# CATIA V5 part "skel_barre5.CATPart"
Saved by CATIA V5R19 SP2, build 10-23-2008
Part number: skel_barre3
Bounding box of the stored display mesh (mm): x 2 to 22, y 3.165 to 19.19, z 5.766 to 6.187
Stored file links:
  E:\TRAVAIL\IAO\skel_barre5.CATPart
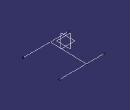
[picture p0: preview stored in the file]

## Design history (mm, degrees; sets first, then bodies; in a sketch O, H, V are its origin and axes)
Body1 (main body)
  Point1 "Point.Mprim": stored without definition
  Point2 "Point.Dprim": stored without definition
  Point3 "Point.Mprim": stored without definition
  Point4 "Point.Dprim": stored without definition
  Line1 "barre_3": type PtPt, FirstPoint Point3, SecondPoint Point4
  Plane1: stored without definition
  Point5 "Point.Mprim": stored without definition
  Line2 "axe_pivot_barre2_barre3": type Normal, RefPoint Point5, RefSkin Plane1, Start 0, End 20
  Plane2: stored without definition
  Point6 "Point.Dprim": stored without definition
  Line3 "axe_pivot_barre3_barre4": type Normal, RefPoint Point6, RefSkin Plane2, Start 0, End 20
